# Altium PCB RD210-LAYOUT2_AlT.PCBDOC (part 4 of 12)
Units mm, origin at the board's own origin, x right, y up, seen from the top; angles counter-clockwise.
Board outline 250 x 123 mm, 4 copper layers (TOP, Mid-Layer 1, Mid-Layer 2, BOTTOM), stack 0.711 mm thick; 1043 components, 659 nets, 2786 pads, 1228 vias.
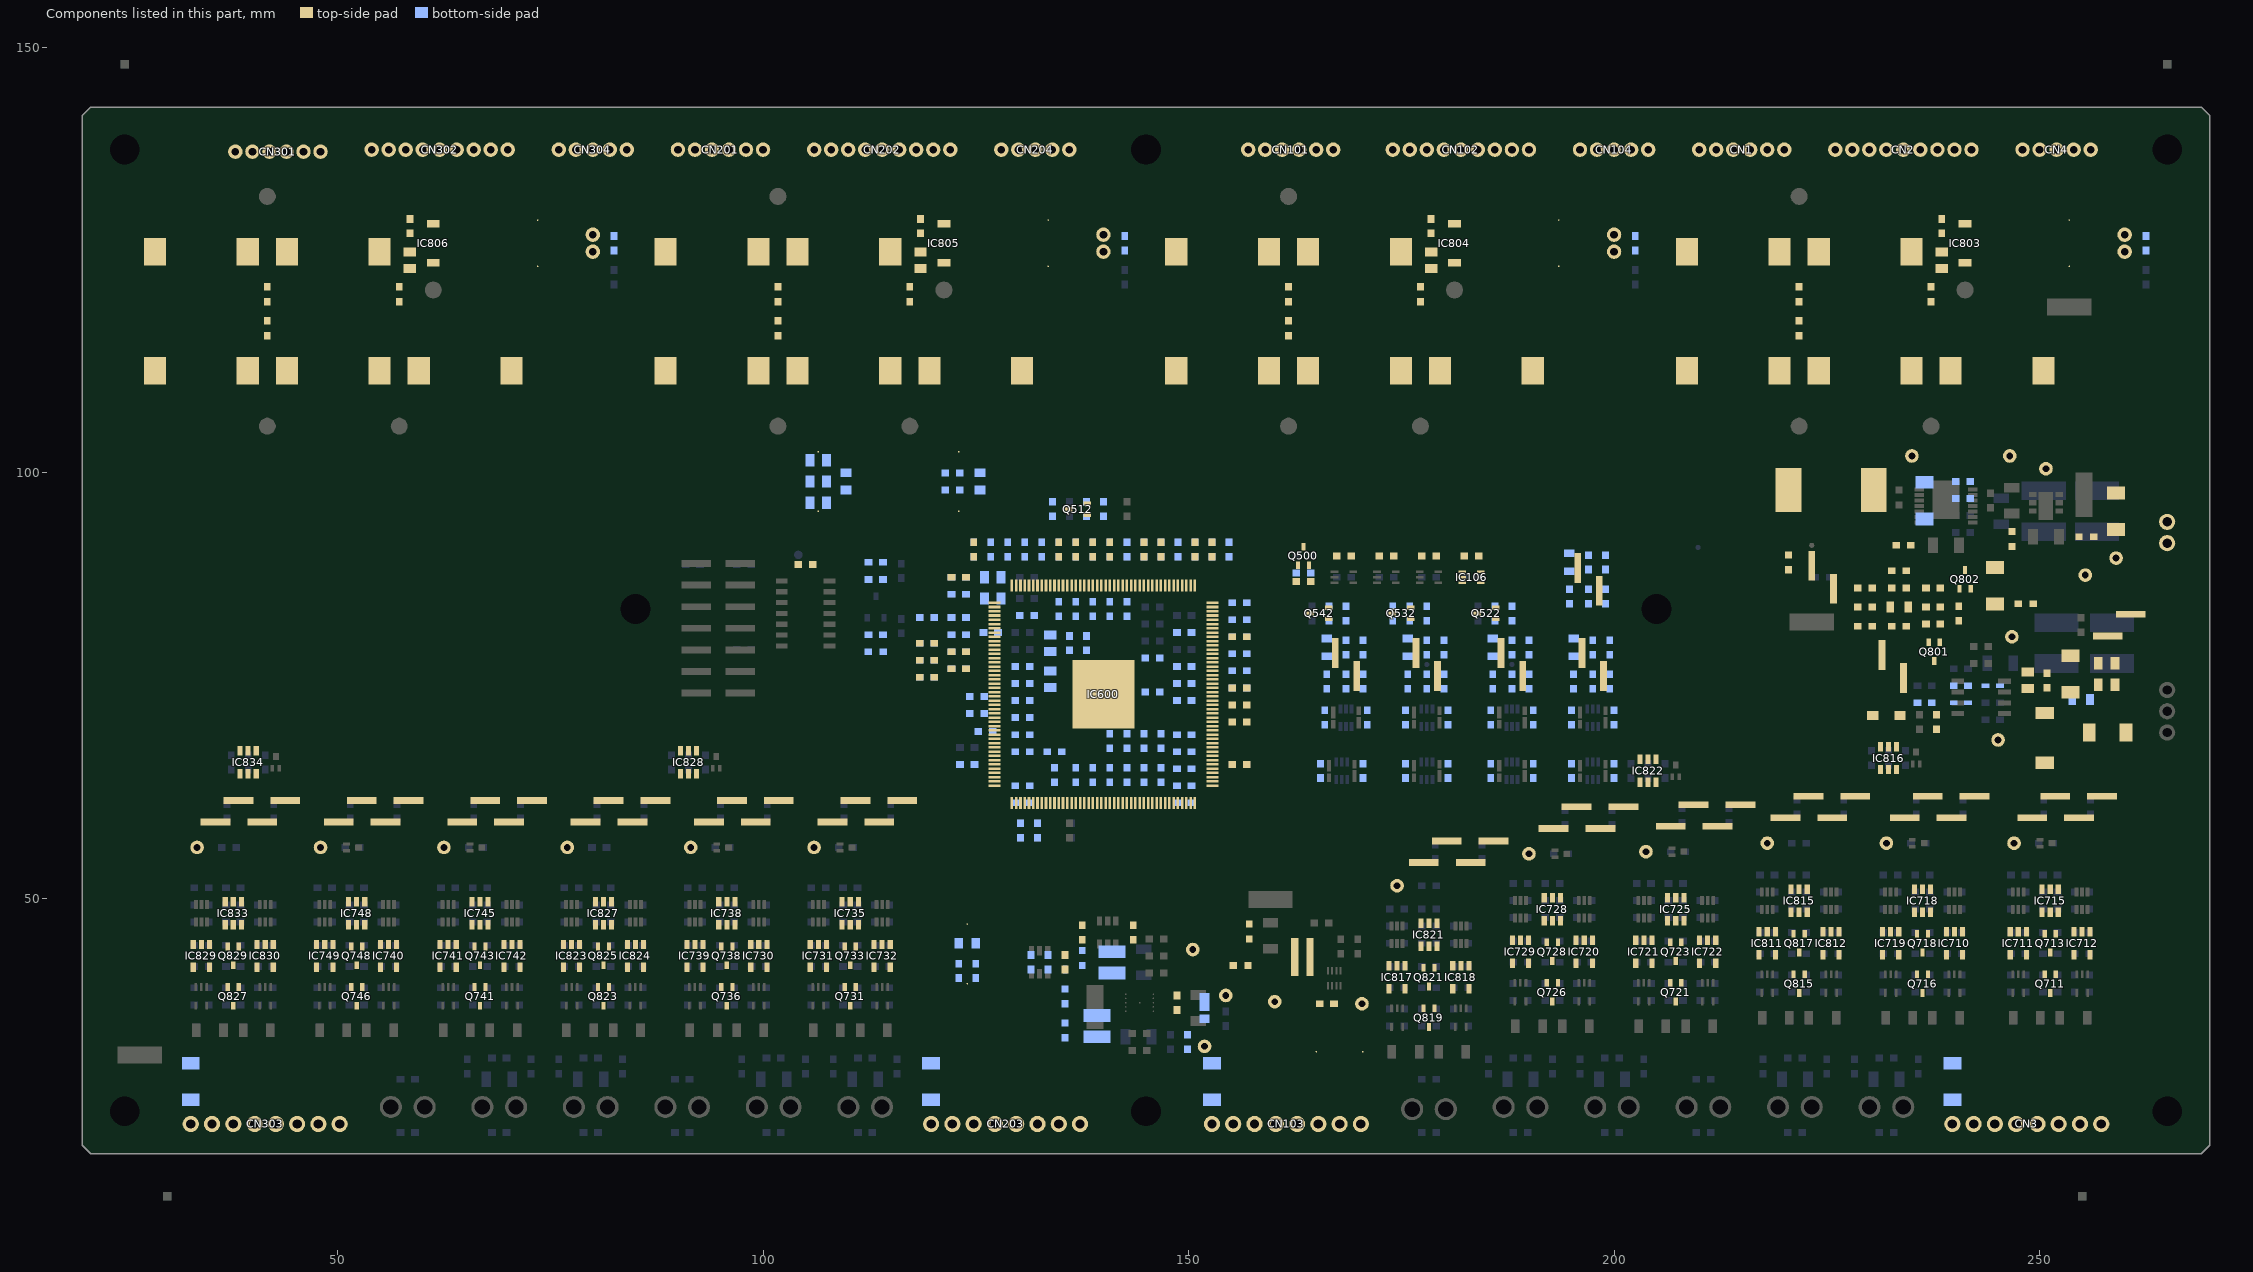
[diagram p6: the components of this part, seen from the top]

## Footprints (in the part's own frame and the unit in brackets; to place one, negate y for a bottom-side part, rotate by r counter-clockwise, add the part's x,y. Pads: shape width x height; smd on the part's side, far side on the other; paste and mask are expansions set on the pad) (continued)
_RS73G1JTTD1002F_+19 [mm] "KC00080BKP"
  rect 0.9x0.8 smd paste-0.9 mask+0: 1(0.85,0) 2(-0.85,0)
_RS73G1JTTD1002F_+20 [mm] "KC00080BKP"
  rect 0.9x0.8 smd paste-0.9 mask+0: 1(0.85,0) 2(-0.85,0)
_RS73G1JTTD1002F_+21 [mm] "KC00080BKP"
  rect 0.9x0.8 smd paste-0.9 mask+0: 1(0.85,0) 2(-0.85,0)
_RS73G1JTTD1002F_+22 [mm] "KC00080BKP"
  rect 0.9x0.8 smd paste-0.9 mask+0: 1(0.85,0) 2(-0.85,0)
_RS73G1JTTD1002F_+23 [mm] "KC00080BKP"
  rect 0.9x0.8 smd paste-0.9 mask+0: 1(0.85,0) 2(-0.85,0)
_RS73G1JTTD1002F_+24 [mm] "KC00080BKP"
  rect 0.9x0.8 smd paste-0.9 mask+0: 1(0.85,0) 2(-0.85,0)
_RS73G1JTTD1002F_+25 [mm] "KC00080BKP"
  rect 0.9x0.8 smd paste-0.9 mask+0: 1(0.85,0) 2(-0.85,0)
_RS73G1JTTD1002F_+26 [mm] "KC00080BKP"
  rect 0.9x0.8 smd paste-0.9 mask+0: 1(0.85,0) 2(-0.85,0)
_RS73G1JTTD1002F_+27 [mm] "KC00080BKP"
  rect 0.9x0.8 smd paste-0.9 mask+0: 1(0.85,0) 2(-0.85,0)
_RS73G1JTTD1002F_+28 [mm] "KC00080BKP"
  rect 0.9x0.8 smd paste-0.9 mask+0: 1(0.85,0) 2(-0.85,0)
_RS73G1JTTD1002F_+29 [mm] "KC00080BKP"
  rect 0.9x0.8 smd paste-0.9 mask+0: 1(0.85,0) 2(-0.85,0)
_RS73G1JTTD1002F_+30 [mm] "KC00080BKP"
  rect 0.9x0.8 smd paste-0.9 mask+0: 1(0.85,0) 2(-0.85,0)
_RS73G1JTTD1002F_+31 [mm] "KC00080BKP"
  rect 0.9x0.8 smd paste-0.9 mask+0: 1(-0.85,0) 2(0.85,0)
_RS73G1JTTD1002F_+32 [mm] "KC00080BKP"
  rect 0.9x0.8 smd paste-0.9 mask+0: 1(0.85,0) 2(-0.85,0)
_RS73G1JTTD1002F_+33 [mm] "KC00080BKP"
  rect 0.9x0.8 smd paste-0.9 mask+0: 1(0.85,0) 2(-0.85,0)
_RS73G1JTTD1002F_+34 [mm] "KC00080BKP"
  rect 0.9x0.8 smd paste-0.9 mask+0: 1(-0.85,0) 2(0.85,0)
_RS73G1JTTD1002F_+35 [mm] "KC00080BKP"
  rect 0.9x0.8 smd paste-0.9 mask+0: 1(0.85,0) 2(-0.85,0)
_RS73G1JTTD1002F_+36 [mm] "KC00080BKP"
  rect 0.9x0.8 smd paste-0.9 mask+0: 1(0.85,0) 2(-0.85,0)
_RS73G1JTTD1002F_+37 [mm] "KC00080BKP"
  rect 0.9x0.8 smd paste-0.9 mask+0: 1(0.85,0) 2(-0.85,0)
_RS73G1JTTD1002F_+38 [mm] "KC00080BKP"
  rect 0.9x0.8 smd paste-0.9 mask+0: 1(0.85,0) 2(-0.85,0)
_RS73G1JTTD1002F_+39 [mm] "KC00080BKP"
  rect 0.9x0.8 smd paste-0.9 mask+0: 1(0.85,0) 2(-0.85,0)
_RS73G1JTTD1002F_+40 [mm] "KC00080BKP"
  rect 0.9x0.8 smd paste-0.9 mask+0: 1(0.85,0) 2(-0.85,0)
_RS73G1JTTD1002F_+41 [mm] "KC00080BKP"
  rect 0.9x0.8 smd paste-0.9 mask+0: 1(0.85,0) 2(-0.85,0)
_RS73G1JTTD1002F_+42 [mm] "KC00080BKP"
  rect 0.9x0.8 smd paste-0.9 mask+0: 1(0.85,0) 2(-0.85,0)
_RS73G1JTTD1002F_+43 [mm] "KC00080BKP"
  rect 0.9x0.8 smd paste-0.9 mask+0: 1(0.85,0) 2(-0.85,0)
_RS73G1JTTD1002F_+44 [mm] "KC00080BKP"
  rect 0.9x0.8 smd paste-0.9 mask+0: 1(0.85,0) 2(-0.85,0)
_RS73G1JTTD1002F_+45 [mm] "KC00080BKP"
  rect 0.9x0.8 smd paste-0.9 mask+0: 1(0.85,0) 2(-0.85,0)
_RS73G1JTTD1002F_+46 [mm] "KC00080BKP"
  rect 0.9x0.8 smd paste-0.9 mask+0: 1(0.85,0) 2(-0.85,0)
_RS73G1JTTD1002F_+47 [mm] "KC00080BKP"
  rect 0.9x0.8 smd paste-0.9 mask+0: 1(0.85,0) 2(-0.85,0)
_RS73G1JTTD1601F_ [mm] "KC00080BKP"
  rect 0.9x0.8 smd paste-0.9 mask+0: 1(0.85,0) 2(-0.85,0)
_RS73G1JTTD1601F_+1 [mm] "KC00080BKP"
  rect 0.9x0.8 smd paste-0.9 mask+0: 1(0.85,0) 2(-0.85,0)
_RS73G1JTTD1601F_+2 [mm] "KC00080BKP"
  rect 0.9x0.8 smd paste-0.9 mask+0: 1(0.85,0) 2(-0.85,0)
_RS73G1JTTD1601F_+3 [mm] "KC00080BKP"
  rect 0.9x0.8 smd paste-0.9 mask+0: 1(0.85,0) 2(-0.85,0)
_RS73G1JTTD1601F_+4 [mm] "KC00080BKP"
  rect 0.9x0.8 smd paste-0.9 mask+0: 1(0.85,0) 2(-0.85,0)
_RS73G1JTTD1601F_+5 [mm] "KC00080BKP"
  rect 0.9x0.8 smd paste-0.9 mask+0: 1(0.85,0) 2(-0.85,0)
_RS73G1JTTD1601F_+6 [mm] "KC00080BKP"
  rect 0.9x0.8 smd paste-0.9 mask+0: 1(0.85,0) 2(-0.85,0)
_RS73G1JTTD1601F_+7 [mm] "KC00080BKP"
  rect 0.9x0.8 smd paste-0.9 mask+0: 1(0.85,0) 2(-0.85,0)
_RS73G1JTTD2201F_ [mm] "KC00080BKP"
  rect 0.9x0.8 smd paste-0.9 mask+0: 1(0.85,0) 2(-0.85,0)
_RS73G1JTTD2201F_+1 [mm] "KC00080BKP"
  rect 0.9x0.8 smd paste-0.9 mask+0: 1(0.85,0) 2(-0.85,0)
_RS73G1JTTD2201F_+2 [mm] "KC00080BKP"
  rect 0.9x0.8 smd paste-0.9 mask+0: 1(-0.85,0) 2(0.85,0)
_RS73G1JTTD2701F_ [mm] "KC00080BKP"
  rect 0.9x0.8 smd paste-0.9 mask+0: 1(0.85,0) 2(-0.85,0)
_RS73G1JTTD2701F_+1 [mm] "KC00080BKP"
  rect 0.9x0.8 smd paste-0.9 mask+0: 1(0.85,0) 2(-0.85,0)
_RS73G1JTTD2701F_+2 [mm] "KC00080BKP"
  rect 0.9x0.8 smd paste-0.9 mask+0: 1(0.85,0) 2(-0.85,0)
_RS73G1JTTD2701F_+3 [mm] "KC00080BKP"
  rect 0.9x0.8 smd paste-0.9 mask+0: 1(0.85,0) 2(-0.85,0)
_RS73G1JTTD4701F_ [mm] "KC00080BKP"
  rect 0.9x0.8 smd paste-0.9 mask+0: 1(-0.85,0) 2(0.85,0)
_RS73G1JTTD4701F_+1 [mm] "KC00080BKP"
  rect 0.9x0.8 smd paste-0.9 mask+0: 1(-0.85,0) 2(0.85,0)
_RS73G1JTTD4701F_+2 [mm] "KC00080BKP"
  rect 0.9x0.8 smd paste-0.9 mask+0: 1(-0.85,0) 2(0.85,0)
_RS73G1JTTD4701F_+3 [mm] "KC00080BKP"
  rect 0.9x0.8 smd paste-0.9 mask+0: 1(-0.85,0) 2(0.85,0)
_RS73G1JTTD4701F_+4 [mm] "KC00080BKP"
  rect 0.9x0.8 smd paste-0.9 mask+0: 1(-0.85,0) 2(0.85,0)
_RS73G1JTTD4701F_+5 [mm] "KC00080BKP"
  rect 0.9x0.8 smd paste-0.9 mask+0: 1(-0.85,0) 2(0.85,0)
_RS73G1JTTD4701F_+6 [mm] "KC00080BKP"
  rect 0.9x0.8 smd paste-0.9 mask+0: 1(-0.85,0) 2(0.85,0)
_RS73G1JTTD4701F_+7 [mm] "KC00080BKP"
  rect 0.9x0.8 smd paste-0.9 mask+0: 1(-0.85,0) 2(0.85,0)
_RS73G1JTTD4701F_+8 [mm] "KC00080BKP"
  rect 0.9x0.8 smd paste-0.9 mask+0: 1(0.85,0) 2(-0.85,0)
_RS73G1JTTD4701F_+9 [mm] "KC00080BKP"
  rect 0.9x0.8 smd paste-0.9 mask+0: 1(0.85,0) 2(-0.85,0)
_RS73G1JTTD4701F_+10 [mm] "KC00080BKP"
  rect 0.9x0.8 smd paste-0.9 mask+0: 1(0.85,0) 2(-0.85,0)
_RS73G1JTTD4701F_+11 [mm] "KC00080BKP"
  rect 0.9x0.8 smd paste-0.9 mask+0: 1(0.85,0) 2(-0.85,0)
_RS73G1JTTD4701F_+12 [mm] "KC00080BKP"
  rect 0.9x0.8 smd paste-0.9 mask+0: 1(-0.85,0) 2(0.85,0)
_RS73G1JTTD4701F_+13 [mm] "KC00080BKP"
  rect 0.9x0.8 smd paste-0.9 mask+0: 1(0.85,0) 2(-0.85,0)
_RS73G1JTTD4701F_+14 [mm] "KC00080BKP"
  rect 0.9x0.8 smd paste-0.9 mask+0: 1(-0.85,0) 2(0.85,0)
_RS73G1JTTD4701F_+15 [mm] "KC00080BKP"
  rect 0.9x0.8 smd paste-0.9 mask+0: 1(-0.85,0) 2(0.85,0)
_RS73G1JTTD5602F_ [mm] "KC00080BKP"
  rect 0.9x0.8 smd paste-0.9 mask+0: 1(0.85,0) 2(-0.85,0)
_RS73G1JTTD5602F_+1 [mm] "KC00080BKP"
  rect 0.9x0.8 smd paste-0.9 mask+0: 1(-0.85,0) 2(0.85,0)
_SG73P1JTTD1R60F_ [mm] "KC00080BKP"
  rect 0.9x0.8 smd paste-0.9 mask+0: 1(-0.85,0) 2(0.85,0)
_SG73P1JTTD1801F_ [mm] "KC00080BKP"
  rect 0.9x0.8 smd paste-0.9 mask+0: 1(0.85,0) 2(-0.85,0)
_SG73P1JTTD1801F_+1 [mm] "KC00080BKP"
  rect 0.9x0.8 smd paste-0.9 mask+0: 1(0.85,0) 2(-0.85,0)
_SG73P1JTTD1801F_+2 [mm] "KC00080BKP"
  rect 0.9x0.8 smd paste-0.9 mask+0: 1(0.85,0) 2(-0.85,0)
_SG73P1JTTD1801F_+3 [mm] "KC00080BKP"
  rect 0.9x0.8 smd paste-0.9 mask+0: 1(0.85,0) 2(-0.85,0)
_SG73P1JTTD1801F_+4 [mm] "KC00080BKP"
  rect 0.9x0.8 smd paste-0.9 mask+0: 1(0.85,0) 2(-0.85,0)
_SG73P1JTTD1801F_+5 [mm] "KC00080BKP"
  rect 0.9x0.8 smd paste-0.9 mask+0: 1(-0.85,0) 2(0.85,0)
_SG73P1JTTD2202F_ [mm] "KC00080BKP"
  rect 0.9x0.8 smd paste-0.9 mask+0: 1(-0.85,0) 2(0.85,0)
_SG73P1JTTD2202F_+1 [mm] "KC00080BKP"
  rect 0.9x0.8 smd paste-0.9 mask+0: 1(0.85,0) 2(-0.85,0)
_SG73P1JTTD2202F_+2 [mm] "KC00080BKP"
  rect 0.9x0.8 smd paste-0.9 mask+0: 1(0.85,0) 2(-0.85,0)
_SG73P1JTTD2202F_+3 [mm] "KC00080BKP"
  rect 0.9x0.8 smd paste-0.9 mask+0: 1(0.85,0) 2(-0.85,0)
_SG73P1JTTD2202F_+4 [mm] "KC00080BKP"
  rect 0.9x0.8 smd paste-0.9 mask+0: 1(0.85,0) 2(-0.85,0)
_SG73P1JTTD2202F_+5 [mm] "KC00080BKP"
  rect 0.9x0.8 smd paste-0.9 mask+0: 1(0.85,0) 2(-0.85,0)
_SG73P1JTTD2202F_+6 [mm] "KC00080BKP"
  rect 0.9x0.8 smd paste-0.9 mask+0: 1(0.85,0) 2(-0.85,0)
_SG73P1JTTD2202F_+7 [mm] "KC00080BKP"
  rect 0.9x0.8 smd paste-0.9 mask+0: 1(0.85,0) 2(-0.85,0)
_SG73P1JTTD2202F_+8 [mm] "KC00080BKP"
  rect 0.9x0.8 smd paste-0.9 mask+0: 1(0.85,0) 2(-0.85,0)
_SG73P1JTTD2202F_+9 [mm] "KC00080BKP"
  rect 0.9x0.8 smd paste-0.9 mask+0: 1(0.85,0) 2(-0.85,0)
_SG73P1JTTD2202F_+10 [mm] "KC00080BKP"
  rect 0.9x0.8 smd paste-0.9 mask+0: 1(-0.85,0) 2(0.85,0)
_SG73P1JTTD2202F_+11 [mm] "KC00080BKP"
  rect 0.9x0.8 smd paste-0.9 mask+0: 1(-0.85,0) 2(0.85,0)
_SG73P1JTTD2202F_+12 [mm] "KC00080BKP"
  rect 0.9x0.8 smd paste-0.9 mask+0: 1(-0.85,0) 2(0.85,0)
_SG73P1JTTD2202F_+13 [mm] "KC00080BKP"
  rect 0.9x0.8 smd paste-0.9 mask+0: 1(-0.85,0) 2(0.85,0)
_SG73P1JTTD8201F_ [mm] "KC00080BKP"
  rect 0.9x0.8 smd paste-0.9 mask+0: 1(0.85,0) 2(-0.85,0)
_SG73P1JTTD8201F_+1 [mm] "KC00080BKP"
  rect 0.9x0.8 smd paste-0.9 mask+0: 1(0.85,0) 2(-0.85,0)
_SG73P1JTTD8201F_+2 [mm] "KC00080BKP"
  rect 0.9x0.8 smd paste-0.9 mask+0: 1(0.85,0) 2(-0.85,0)
_SG73P1JTTD8201F_+3 [mm] "KC00080BKP"
  rect 0.9x0.8 smd paste-0.9 mask+0: 1(0.85,0) 2(-0.85,0)
_SG73P1JTTD8201F_+4 [mm] "KC00080BKP"
  rect 0.9x0.8 smd paste-0.9 mask+0: 1(0.85,0) 2(-0.85,0)
_SG73P1JTTD8201F_+5 [mm] "KC00080BKP"
  rect 0.9x0.8 smd paste-0.9 mask+0: 1(-0.85,0) 2(0.85,0)
_SG73P2ATTD100J_ [mm] "KC00080BKP"
  rect 0.9x1.25 smd paste-1.25 mask+0: 1(1.05,0) 2(-1.05,0)
_SG73P2ATTD101J_ [mm] "KC00080BKP"
  rect 0.9x1.25 smd paste-1.25 mask+0: 1(1.05,0) 2(-1.05,0)
_SG73P2ATTD101J_+1 [mm] "KC00080BKP"
  rect 0.9x1.25 smd paste-1.25 mask+0: 1(1.05,0) 2(-1.05,0)
_SG73P2ATTD101J_+2 [mm] "KC00080BKP"
  rect 0.9x1.25 smd paste-1.25 mask+0: 1(1.05,0) 2(-1.05,0)
_SG73P2ATTD101J_+3 [mm] "KC00080BKP"
  rect 0.9x1.25 smd paste-1.25 mask+0: 1(1.05,0) 2(-1.05,0)
_SG73P2ATTD101J_+4 [mm] "KC00080BKP"
  rect 0.9x1.25 smd paste-1.25 mask+0: 1(1.05,0) 2(-1.05,0)
_SG73P2ATTD101J_+5 [mm] "KC00080BKP"
  rect 0.9x1.25 smd paste-1.25 mask+0: 1(-1.05,0) 2(1.05,0)
_TLRZ1JTTD_ [mm] "KC00080BKP"
  rect 0.85x0.8 smd paste-0.85 mask+0: 1(-0.875,0) 2(0.875,0)
_TLRZ1JTTD_+1 [mm] "KC00080BKP"
  rect 0.85x0.8 smd paste-0.85 mask+0: 1(-0.875,0) 2(0.875,0)
_TLRZ1JTTD_+2 [mm] "KC00080BKP"
  rect 0.85x0.8 smd paste-0.85 mask+0: 1(-0.875,0) 2(0.875,0)
_TLRZ1JTTD_+3 [mm] "KC00080BKP"
  rect 0.85x0.8 smd paste-0.85 mask+0: 1(-0.875,0) 2(0.875,0)
_TLRZ1JTTD_+4 [mm] "KC00080BKP"
  rect 0.85x0.8 smd paste-0.85 mask+0: 1(-0.875,0) 2(0.875,0)
_TLRZ1JTTD_+5 [mm] "KC00080BKP"
  rect 0.85x0.8 smd paste-0.85 mask+0: 1(-0.875,0) 2(0.875,0)
_TLRZ1JTTD_+6 [mm] "KC00080BKP"
  rect 0.85x0.8 smd paste-0.85 mask+0: 1(-0.875,0) 2(0.875,0)
_TLRZ1JTTD_+7 [mm] "KC00080BKP"
  rect 0.85x0.8 smd paste-0.85 mask+0: 1(-0.875,0) 2(0.875,0)
_TLRZ1JTTD_+8 [mm] "KC00080BKP"
  rect 0.85x0.8 smd paste-0.85 mask+0: 1(-0.875,0) 2(0.875,0)
_TLRZ1JTTD_+9 [mm] "KC00080BKP"
  rect 0.85x0.8 smd paste-0.85 mask+0: 1(-0.875,0) 2(0.875,0)
_TLRZ1JTTD_+10 [mm] "KC00080BKP"
  rect 0.85x0.8 smd paste-0.85 mask+0: 1(-0.875,0) 2(0.875,0)
_TLRZ1JTTD_+11 [mm] "KC00080BKP"
  rect 0.85x0.8 smd paste-0.85 mask+0: 1(-0.875,0) 2(0.875,0)
_TLRZ1JTTD_+12 [mm] "KC00080BKP"
  rect 0.85x0.8 smd paste-0.85 mask+0: 1(-0.875,0) 2(0.875,0)
_TLRZ1JTTD_+13 [mm] "KC00080BKP"
  rect 0.85x0.8 smd paste-0.85 mask+0: 1(0.875,0) 2(-0.875,0)
_TLRZ1JTTD_+14 [mm] "KC00080BKP"
  rect 0.85x0.8 smd paste-0.85 mask+0: 1(-0.875,0) 2(0.875,0)
_TLRZ1JTTD_+15 [mm] "KC00080BKP"
  rect 0.85x0.8 smd paste-0.85 mask+0: 1(-0.875,0) 2(0.875,0)
_TLRZ1JTTD_+16 [mm] "KC00080BKP"
  rect 0.85x0.8 smd paste-0.85 mask+0: 1(0.875,0) 2(-0.875,0)
_TLRZ1JTTD_+17 [mm] "KC00080BKP"
  rect 0.85x0.8 smd paste-0.85 mask+0: 1(-0.875,0) 2(0.875,0)
_TLRZ1JTTD_+18 [mm] "KC00080BKP"
  rect 0.85x0.8 smd paste-0.85 mask+0: 1(-0.875,0) 2(0.875,0)
_TLRZ1JTTD_+19 [mm] "KC00080BKP"
  rect 0.85x0.8 smd paste-0.85 mask+0: 1(0.875,0) 2(-0.875,0)
_TLRZ1JTTD_+20 [mm] "KC00080BKP"
  rect 0.85x0.8 smd paste-0.85 mask+0: 1(-0.875,0) 2(0.875,0)
_TLRZ1JTTD_+21 [mm] "KC00080BKP"
  rect 0.85x0.8 smd paste-0.85 mask+0: 1(0.875,0) 2(-0.875,0)
_TLVH431AQDBVRQ1_ [mm] "KC00080BKP"
  rect 0.6x1.1 smd paste-1.1 mask+0: 1(-0.95,-1.35) 2(0,-1.35) 3(0.95,-1.35) 4(0.95,1.35) 5(-0.95,1.35)
_TLVH431AQDBVRQ1_+1 [mm] "KC00080BKP"
  rect 0.6x1.1 smd paste-1.1 mask+0: 1(-0.95,-1.35) 2(0,-1.35) 3(0.95,-1.35) 4(0.95,1.35) 5(-0.95,1.35)
_TLVH431AQDBVRQ1_+2 [mm] "KC00080BKP"
  rect 0.6x1.1 smd paste-1.1 mask+0: 1(-0.95,-1.35) 2(0,-1.35) 3(0.95,-1.35) 4(0.95,1.35) 5(-0.95,1.35)
_TLVH431AQDBVRQ1_+3 [mm] "KC00080BKP"
  rect 0.6x1.1 smd paste-1.1 mask+0: 1(-0.95,-1.35) 2(0,-1.35) 3(0.95,-1.35) 4(0.95,1.35) 5(-0.95,1.35)
_TLVH431AQDBVRQ1_+4 [mm] "KC00080BKP"
  rect 0.6x1.1 smd paste-1.1 mask+0: 1(-0.95,-1.35) 2(0,-1.35) 3(0.95,-1.35) 4(0.95,1.35) 5(-0.95,1.35)
_TLVH431AQDBVRQ1_+5 [mm] "KC00080BKP"
  rect 0.6x1.1 smd paste-1.1 mask+0: 1(-0.95,-1.35) 2(0,-1.35) 3(0.95,-1.35) 4(0.95,1.35) 5(-0.95,1.35)
_TLVH431AQDBVRQ1_+6 [mm] "KC00080BKP"
  rect 0.6x1.1 smd paste-1.1 mask+0: 1(-0.95,-1.35) 2(0,-1.35) 3(0.95,-1.35) 4(0.95,1.35) 5(-0.95,1.35)
_TLVH431AQDBVRQ1_+7 [mm] "KC00080BKP"
  rect 0.6x1.1 smd paste-1.1 mask+0: 1(-0.95,-1.35) 2(0,-1.35) 3(0.95,-1.35) 4(0.95,1.35) 5(-0.95,1.35)
_TLVH431AQDBVRQ1_+8 [mm] "KC00080BKP"
  rect 0.6x1.1 smd paste-1.1 mask+0: 1(-0.95,-1.35) 2(0,-1.35) 3(0.95,-1.35) 4(0.95,1.35) 5(-0.95,1.35)
_TLVH431AQDBVRQ1_+9 [mm] "KC00080BKP"
  rect 0.6x1.1 smd paste-1.1 mask+0: 1(-0.95,-1.35) 2(0,-1.35) 3(0.95,-1.35) 4(0.95,1.35) 5(-0.95,1.35)
_TLVH431AQDBVRQ1_+10 [mm] "KC00080BKP"
  rect 0.6x1.1 smd paste-1.1 mask+0: 1(-0.95,-1.35) 2(0,-1.35) 3(0.95,-1.35) 4(0.95,1.35) 5(-0.95,1.35)
_TLVH431AQDBVRQ1_+11 [mm] "KC00080BKP"
  rect 0.6x1.1 smd paste-1.1 mask+0: 1(-0.95,-1.35) 2(0,-1.35) 3(0.95,-1.35) 4(0.95,1.35) 5(-0.95,1.35)
_TLVH431AQDBVRQ1_+12 [mm] "KC00080BKP"
  rect 0.6x1.1 smd paste-1.1 mask+0: 1(-0.95,-1.35) 2(0,-1.35) 3(0.95,-1.35) 4(0.95,1.35) 5(-0.95,1.35)
_TLVH431AQDBVRQ1_+13 [mm] "KC00080BKP"
  rect 0.6x1.1 smd paste-1.1 mask+0: 1(-0.95,-1.35) 2(0,-1.35) 3(0.95,-1.35) 4(0.95,1.35) 5(-0.95,1.35)
_TLVH431AQDBVRQ1_+14 [mm] "KC00080BKP"
  rect 0.6x1.1 smd paste-1.1 mask+0: 1(-0.95,-1.35) 2(0,-1.35) 3(0.95,-1.35) 4(0.95,1.35) 5(-0.95,1.35)
_TLVH431AQDBVRQ1_+15 [mm] "KC00080BKP"
  rect 0.6x1.1 smd paste-1.1 mask+0: 1(-0.95,-1.35) 2(0,-1.35) 3(0.95,-1.35) 4(0.95,1.35) 5(-0.95,1.35)
_TLVH431AQDBVRQ1_+16 [mm] "KC00080BKP"
  rect 0.6x1.1 smd paste-1.1 mask+0: 1(-0.95,-1.35) 2(0,-1.35) 3(0.95,-1.35) 4(0.95,1.35) 5(-0.95,1.35)
_TLVH431AQDBVRQ1_+17 [mm] "KC00080BKP"
  rect 0.6x1.1 smd paste-1.1 mask+0: 1(-0.95,-1.35) 2(0,-1.35) 3(0.95,-1.35) 4(0.95,1.35) 5(-0.95,1.35)
_TLVH431AQDBVRQ1_+18 [mm] "KC00080BKP"
  rect 0.6x1.1 smd paste-1.1 mask+0: 1(-0.95,-1.35) 2(0,-1.35) 3(0.95,-1.35) 4(0.95,1.35) 5(-0.95,1.35)
_TLVH431AQDBVRQ1_+19 [mm] "KC00080BKP"
  rect 0.6x1.1 smd paste-1.1 mask+0: 1(-0.95,-1.35) 2(0,-1.35) 3(0.95,-1.35) 4(0.95,1.35) 5(-0.95,1.35)
_TLVH431AQDBVRQ1_+20 [mm] "KC00080BKP"
  rect 0.6x1.1 smd paste-1.1 mask+0: 1(-0.95,-1.35) 2(0,-1.35) 3(0.95,-1.35) 4(0.95,1.35) 5(-0.95,1.35)
_TLVH431AQDBVRQ1_+21 [mm] "KC00080BKP"
  rect 0.6x1.1 smd paste-1.1 mask+0: 1(-0.95,-1.35) 2(0,-1.35) 3(0.95,-1.35) 4(0.95,1.35) 5(-0.95,1.35)
_TLVH431AQDBVRQ1_+22 [mm] "KC00080BKP"
  rect 0.6x1.1 smd paste-1.1 mask+0: 1(-0.95,-1.35) 2(0,-1.35) 3(0.95,-1.35) 4(0.95,1.35) 5(-0.95,1.35)
_TLVH431AQDBVRQ1_+23 [mm] "KC00080BKP"
  rect 0.6x1.1 smd paste-1.1 mask+0: 1(-0.95,-1.35) 2(0,-1.35) 3(0.95,-1.35) 4(0.95,1.35) 5(-0.95,1.35)
_TMS320F28377SPTP_ [mm] "KC00080BKP"
  rect 0.3x1.4 smd paste-1.4 mask+0: 1(-10.75,-12.8) 2(-10.25,-12.8) 3(-9.75,-12.8) 4(-9.25,-12.8) 5(-8.75,-12.8) 6(-8.25,-12.8) 7(-7.75,-12.8) 8(-7.25,-12.8) 9(-6.75,-12.8) 10(-6.25,-12.8) 11(-5.75,-12.8) 12(-5.25,-12.8) 13(-4.75,-12.8) 14(-4.25,-12.8) 15(-3.75,-12.8) 16(-3.25,-12.8) 17(-2.75,-12.8) 18(-2.25,-12.8) 19(-1.75,-12.8) 20(-1.25,-12.8) 21(-0.75,-12.8) 22(-0.25,-12.8) 23(0.25,-12.8) 24(0.75,-12.8) 25(1.25,-12.8) 26(1.75,-12.8) 27(2.25,-12.8) 28(2.75,-12.8) 29(3.25,-12.8) 30(3.75,-12.8) 31(4.25,-12.8) 32(4.75,-12.8) 33(5.25,-12.8) 34(5.75,-12.8) 35(6.25,-12.8) 36(6.75,-12.8) 37(7.25,-12.8) 38(7.75,-12.8) 39(8.25,-12.8) 40(8.75,-12.8) 41(9.25,-12.8) 42(9.75,-12.8) 43(10.25,-12.8) 44(10.75,-12.8) 89(10.75,12.8) 90(10.25,12.8) 91(9.75,12.8) 92(9.25,12.8) 93(8.75,12.8) 94(8.25,12.8) 95(7.75,12.8) 96(7.25,12.8) 97(6.75,12.8) 98(6.25,12.8) 99(5.75,12.8) 100(5.25,12.8) 101(4.75,12.8) 102(4.25,12.8) 103(3.75,12.8) 104(3.25,12.8) 105(2.75,12.8) 106(2.25,12.8) 107(1.75,12.8) 108(1.25,12.8) 109(0.75,12.8) 110(0.25,12.8) 111(-0.25,12.8) 112(-0.75,12.8) 113(-1.25,12.8) 114(-1.75,12.8) 115(-2.25,12.8) 116(-2.75,12.8) 117(-3.25,12.8) 118(-3.75,12.8) 119(-4.25,12.8) 120(-4.75,12.8) 121(-5.25,12.8) 122(-5.75,12.8) 123(-6.25,12.8) 124(-6.75,12.8) 125(-7.25,12.8) 126(-7.75,12.8) 127(-8.25,12.8) 128(-8.75,12.8) 129(-9.25,12.8) 130(-9.75,12.8) 131(-10.25,12.8) 132(-10.75,12.8)
  rect 1.4x0.3 smd paste-1.4 mask+0: 45(12.8,-10.75) 46(12.8,-10.25) 47(12.8,-9.75) 48(12.8,-9.25) 49(12.8,-8.75) 50(12.8,-8.25) 51(12.8,-7.75) 52(12.8,-7.25) 53(12.8,-6.75) 54(12.8,-6.25) 55(12.8,-5.75) 56(12.8,-5.25) 57(12.8,-4.75) 58(12.8,-4.25) 59(12.8,-3.75) 60(12.8,-3.25) 61(12.8,-2.75) 62(12.8,-2.25) 63(12.8,-1.75) 64(12.8,-1.25) 65(12.8,-0.75) 66(12.8,-0.25) 67(12.8,0.25) 68(12.8,0.75) 69(12.8,1.25) 70(12.8,1.75) 71(12.8,2.25) 72(12.8,2.75) 73(12.8,3.25) 74(12.8,3.75) 75(12.8,4.25) 76(12.8,4.75) 77(12.8,5.25) 78(12.8,5.75) 79(12.8,6.25) 80(12.8,6.75) 81(12.8,7.25) 82(12.8,7.75) 83(12.8,8.25) 84(12.8,8.75) 85(12.8,9.25) 86(12.8,9.75) 87(12.8,10.25) 88(12.8,10.75) 133(-12.8,10.75) 134(-12.8,10.25) 135(-12.8,9.75) 136(-12.8,9.25) 137(-12.8,8.75) 138(-12.8,8.25) 139(-12.8,7.75) 140(-12.8,7.25) 141(-12.8,6.75) 142(-12.8,6.25) 143(-12.8,5.75) 144(-12.8,5.25) 145(-12.8,4.75) 146(-12.8,4.25) 147(-12.8,3.75) 148(-12.8,3.25) 149(-12.8,2.75) 150(-12.8,2.25) 151(-12.8,1.75) 152(-12.8,1.25) 153(-12.8,0.75) 154(-12.8,0.25) 155(-12.8,-0.25) 156(-12.8,-0.75) 157(-12.8,-1.25) 158(-12.8,-1.75) 159(-12.8,-2.25) 160(-12.8,-2.75) 161(-12.8,-3.25) 162(-12.8,-3.75) 163(-12.8,-4.25) 164(-12.8,-4.75) 165(-12.8,-5.25) 166(-12.8,-5.75) 167(-12.8,-6.25) 168(-12.8,-6.75) 169(-12.8,-7.25) 170(-12.8,-7.75) 171(-12.8,-8.25) 172(-12.8,-8.75) 173(-12.8,-9.25) 174(-12.8,-9.75) 175(-12.8,-10.25) 176(-12.8,-10.75)
  rect 7.3x8 smd paste-8 mask+0: 177(0,0)
_TS5A3159QDBVRQ1_ [mm] "KC00080BKP"
  rect 0.6x1.1 smd paste-1.1 mask+0: 1(-0.95,-1.35) 2(0,-1.35) 3(0.95,-1.35) 4(0.95,1.35) 5(0,1.35) 6(-0.95,1.35)
_TS5A3159QDBVRQ1_+1 [mm] "KC00080BKP"
  rect 0.6x1.1 smd paste-1.1 mask+0: 1(-0.95,-1.35) 2(0,-1.35) 3(0.95,-1.35) 4(0.95,1.35) 5(0,1.35) 6(-0.95,1.35)
_TS5A3159QDBVRQ1_+2 [mm] "KC00080BKP"
  rect 0.6x1.1 smd paste-1.1 mask+0: 1(-0.95,-1.35) 2(0,-1.35) 3(0.95,-1.35) 4(0.95,1.35) 5(0,1.35) 6(-0.95,1.35)
_TS5A3159QDBVRQ1_+3 [mm] "KC00080BKP"
  rect 0.6x1.1 smd paste-1.1 mask+0: 1(-0.95,-1.35) 2(0,-1.35) 3(0.95,-1.35) 4(0.95,1.35) 5(0,1.35) 6(-0.95,1.35)
_TS5A3159QDBVRQ1_+4 [mm] "KC00080BKP"
  rect 0.6x1.1 smd paste-1.1 mask+0: 1(-0.95,-1.35) 2(0,-1.35) 3(0.95,-1.35) 4(0.95,1.35) 5(0,1.35) 6(-0.95,1.35)
_TS5A3159QDBVRQ1_+5 [mm] "KC00080BKP"
  rect 0.6x1.1 smd paste-1.1 mask+0: 1(-0.95,-1.35) 2(0,-1.35) 3(0.95,-1.35) 4(0.95,1.35) 5(0,1.35) 6(-0.95,1.35)
_TS5A3159QDBVRQ1_+6 [mm] "KC00080BKP"
  rect 0.6x1.1 smd paste-1.1 mask+0: 1(-0.95,-1.35) 2(0,-1.35) 3(0.95,-1.35) 4(0.95,1.35) 5(0,1.35) 6(-0.95,1.35)
_TS5A3159QDBVRQ1_+7 [mm] "KC00080BKP"
  rect 0.6x1.1 smd paste-1.1 mask+0: 1(-0.95,-1.35) 2(0,-1.35) 3(0.95,-1.35) 4(0.95,1.35) 5(0,1.35) 6(-0.95,1.35)
_TS5A3159QDBVRQ1_+8 [mm] "KC00080BKP"
  rect 0.6x1.1 smd paste-1.1 mask+0: 1(-0.95,-1.35) 2(0,-1.35) 3(0.95,-1.35) 4(0.95,1.35) 5(0,1.35) 6(-0.95,1.35)
_TS5A3159QDBVRQ1_+9 [mm] "KC00080BKP"
  rect 0.6x1.1 smd paste-1.1 mask+0: 1(-0.95,-1.35) 2(0,-1.35) 3(0.95,-1.35) 4(0.95,1.35) 5(0,1.35) 6(-0.95,1.35)
_TS5A3159QDBVRQ1_+10 [mm] "KC00080BKP"
  rect 0.6x1.1 smd paste-1.1 mask+0: 1(-0.95,-1.35) 2(0,-1.35) 3(0.95,-1.35) 4(0.95,1.35) 5(0,1.35) 6(-0.95,1.35)
_TS5A3159QDBVRQ1_+11 [mm] "KC00080BKP"
  rect 0.6x1.1 smd paste-1.1 mask+0: 1(-0.95,-1.35) 2(0,-1.35) 3(0.95,-1.35) 4(0.95,1.35) 5(0,1.35) 6(-0.95,1.35)
_TS5A3159QDBVRQ1_+12 [mm] "KC00080BKP"
  rect 0.6x1.1 smd paste-1.1 mask+0: 1(-0.95,-1.35) 2(0,-1.35) 3(0.95,-1.35) 4(0.95,1.35) 5(0,1.35) 6(-0.95,1.35)
_TS5A3159QDBVRQ1_+13 [mm] "KC00080BKP"
  rect 0.6x1.1 smd paste-1.1 mask+0: 1(-0.95,-1.35) 2(0,-1.35) 3(0.95,-1.35) 4(0.95,1.35) 5(0,1.35) 6(-0.95,1.35)
_TS5A3159QDBVRQ1_+14 [mm] "KC00080BKP"
  rect 0.6x1.1 smd paste-1.1 mask+0: 1(-0.95,-1.35) 2(0,-1.35) 3(0.95,-1.35) 4(0.95,1.35) 5(0,1.35) 6(-0.95,1.35)
_TS5A3159QDBVRQ1_+15 [mm] "KC00080BKP"
  rect 0.6x1.1 smd paste-1.1 mask+0: 1(-0.95,-1.35) 2(0,-1.35) 3(0.95,-1.35) 4(0.95,1.35) 5(0,1.35) 6(-0.95,1.35)
_TSW-101-07-G-S_ [mm] "KC00080BKP"
  round 1.6 hole 0.8 paste-1.7 mask+0: 1(0,0)
D2P_CN-5.9x4.5x6-PX2-H0.9 [mm] "KC00080BKP"
  round 1.7 hole 0.9 paste-1.8 mask+0: 1(1,0) 2(-1,0)
D2P_CN-7.4x5.75x7-PX2.5-H1.1 [mm] "KC00080BKP"
  round 1.9 hole 1.1 paste-2 mask+0: 1(1.25,0) 2(-1.25,0)
D5P_CN-11.9x4.5x6-PX2-H0.9 [mm] "KC00080BKP"
  round 1.7 hole 0.9 paste-1.8 mask+0: 1(4,0) 2(2,0) 3(0,0) 4(-2,0) 5(-4,0)
D6P_CN-13.9x4.5x6-PX2-H0.9 [mm] "KC00080BKP"
  round 1.7 hole 0.9 paste-1.8 mask+0: 1(5,0) 2(3,0) 3(1,0) 4(-1,0) 5(-3,0) 6(-5,0)
D8P_CN-22.4x5.75x7-PX2.5-H1.1 [mm] "KC00080BKP"
  round 1.9 hole 1.1 paste-2 mask+0: 1(8.75,0) 2(6.25,0) 3(3.75,0) 4(1.25,0) 5(-1.25,0) 6(-3.75,0) 7(-6.25,0) 8(-8.75,0)
D9P_CN-19.9x4.5x6-PX2-H0.9 [mm] "KC00080BKP"
  round 1.7 hole 0.9 paste-1.8 mask+0: 1(8,0) 2(6,0) 3(4,0) 4(2,0) 5(0,0) 6(-2,0) 7(-4,0) 8(-6,0) 9(-8,0)
S2P_CC-1.6x0.8x0.8-PX1.6 [mm] "KC00080BKP"
  rect 0.9x0.8 smd paste-0.9 mask+0: 1(0.85,0) 2(-0.85,0)
S2P_CC-1.6x0.8x0.8-PX1.6+1 [mm] "KC00080BKP"
  rect 0.9x0.8 smd paste-0.9 mask+0: 1(0.85,0) 2(-0.85,0)
S2P_CC-1.6x0.8x0.8-PX1.6+2 [mm] "KC00080BKP"
  rect 0.9x0.8 smd paste-0.9 mask+0: 1(0.85,0) 2(-0.85,0)
S2P_CC-1.6x0.8x0.8-PX1.6+3 [mm] "KC00080BKP"
  rect 0.9x0.8 smd paste-0.9 mask+0: 1(0.85,0) 2(-0.85,0)
S2P_CC-1.6x0.8x0.8-PX1.6+4 [mm] "KC00080BKP"
  rect 0.9x0.8 smd paste-0.9 mask+0: 1(0.85,0) 2(-0.85,0)
S2P_CC-1.6x0.8x0.8-PX1.6+5 [mm] "KC00080BKP"
  rect 0.9x0.8 smd paste-0.9 mask+0: 1(0.85,0) 2(-0.85,0)
S2P_CC-1.6x0.8x0.8-PX1.6+6 [mm] "KC00080BKP"
  rect 0.9x0.8 smd paste-0.9 mask+0: 1(0.85,0) 2(-0.85,0)
S2P_CC-1.6x0.8x0.8-PX1.6+7 [mm] "KC00080BKP"
  rect 0.9x0.8 smd paste-0.9 mask+0: 1(0.85,0) 2(-0.85,0)
S2P_CC-1.6x0.8x0.8-PX1.6+8 [mm] "KC00080BKP"
  rect 0.9x0.8 smd paste-0.9 mask+0: 1(0.85,0) 2(-0.85,0)
S2P_CC-1.6x0.8x0.8-PX1.6+9 [mm] "KC00080BKP"
  rect 0.9x0.8 smd paste-0.9 mask+0: 1(0.85,0) 2(-0.85,0)
S2P_CC-1.6x0.8x0.8-PX1.6+10 [mm] "KC00080BKP"
  rect 0.9x0.8 smd paste-0.9 mask+0: 1(0.85,0) 2(-0.85,0)
S2P_CC-1.6x0.8x0.8-PX1.6+11 [mm] "KC00080BKP"
  rect 0.9x0.8 smd paste-0.9 mask+0: 1(-0.85,0) 2(0.85,0)
S2P_CC-1.6x0.8x0.8-PX1.6+12 [mm] "KC00080BKP"
  rect 0.9x0.8 smd paste-0.9 mask+0: 1(-0.85,0) 2(0.85,0)
S2P_CC-1.6x0.8x0.8-PX1.6+13 [mm] "KC00080BKP"
  rect 0.9x0.8 smd paste-0.9 mask+0: 1(0.85,0) 2(-0.85,0)
S2P_CC-1.6x0.8x0.8-PX1.6+14 [mm] "KC00080BKP"
  rect 0.9x0.8 smd paste-0.9 mask+0: 1(-0.85,0) 2(0.85,0)
S2P_CC-1.6x0.8x0.8-PX1.6+15 [mm] "KC00080BKP"
  rect 0.9x0.8 smd paste-0.9 mask+0: 1(-0.85,0) 2(0.85,0)
S2P_CC-1.6x0.8x0.8-PX1.6+16 [mm] "KC00080BKP"
  rect 0.9x0.8 smd paste-0.9 mask+0: 1(-0.85,0) 2(0.85,0)
S2P_CC-1.6x0.8x0.8-PX1.6+17 [mm] "KC00080BKP"
  rect 0.9x0.8 smd paste-0.9 mask+0: 1(0.85,0) 2(-0.85,0)
S2P_CC-1.6x0.8x0.8-PX1.6+18 [mm] "KC00080BKP"
  rect 0.9x0.8 smd paste-0.9 mask+0: 1(-0.85,0) 2(0.85,0)
S2P_CC-1.6x0.8x0.8-PX1.6+19 [mm] "KC00080BKP"
  rect 0.9x0.8 smd paste-0.9 mask+0: 1(-0.85,0) 2(0.85,0)
S2P_CC-1.6x0.8x0.8-PX1.6+20 [mm] "KC00080BKP"
  rect 0.9x0.8 smd paste-0.9 mask+0: 1(-0.85,0) 2(0.85,0)
S2P_CC-1.6x0.8x0.8-PX1.6+21 [mm] "KC00080BKP"
  rect 0.9x0.8 smd paste-0.9 mask+0: 1(-0.85,0) 2(0.85,0)
S2P_CC-1.6x0.8x0.8-PX1.6+22 [mm] "KC00080BKP"
  rect 0.9x0.8 smd paste-0.9 mask+0: 1(0.85,0) 2(-0.85,0)
S2P_CC-1.6x0.8x0.8-PX1.6+23 [mm] "KC00080BKP"
  rect 0.9x0.8 smd paste-0.9 mask+0: 1(-0.85,0) 2(0.85,0)
S2P_CC-1.6x0.8x0.8-PX1.6+24 [mm] "KC00080BKP"
  rect 0.9x0.8 smd paste-0.9 mask+0: 1(0.85,0) 2(-0.85,0)
S2P_CC-1.6x0.8x0.8-PX1.6+25 [mm] "KC00080BKP"
  rect 0.9x0.8 smd paste-0.9 mask+0: 1(0.85,0) 2(-0.85,0)
S2P_CC-1.6x0.8x0.8-PX1.6+26 [mm] "KC00080BKP"
  rect 0.9x0.8 smd paste-0.9 mask+0: 1(0.85,0) 2(-0.85,0)
S2P_CC-1.6x0.8x0.8-PX1.6+27 [mm] "KC00080BKP"
  rect 0.9x0.8 smd paste-0.9 mask+0: 1(-0.85,0) 2(0.85,0)
S2P_CC-1.6x0.8x0.8-PX1.6+28 [mm] "KC00080BKP"
  rect 0.9x0.8 smd paste-0.9 mask+0: 1(0.85,0) 2(-0.85,0)
S2P_CC-1.6x0.8x0.8-PX1.6+29 [mm] "KC00080BKP"
  rect 0.9x0.8 smd paste-0.9 mask+0: 1(0.85,0) 2(-0.85,0)
S2P_CC-1.6x0.8x0.8-PX1.6+30 [mm] "KC00080BKP"
  rect 0.9x0.8 smd paste-0.9 mask+0: 1(0.85,0) 2(-0.85,0)
S2P_CC-1.6x0.8x0.8-PX1.6+31 [mm] "KC00080BKP"
  rect 0.9x0.8 smd paste-0.9 mask+0: 1(0.85,0) 2(-0.85,0)
S2P_CC-1.6x0.8x0.8-PX1.6+32 [mm] "KC00080BKP"
  rect 0.9x0.8 smd paste-0.9 mask+0: 1(0.85,0) 2(-0.85,0)
S2P_CC-1.6x0.8x0.8-PX1.6+33 [mm] "KC00080BKP"
  rect 0.9x0.8 smd paste-0.9 mask+0: 1(0.85,0) 2(-0.85,0)
S2P_CC-1.6x0.8x0.8-PX1.6+34 [mm] "KC00080BKP"
  rect 0.9x0.8 smd paste-0.9 mask+0: 1(0.85,0) 2(-0.85,0)
S2P_CC-1.6x0.8x0.8-PX1.6+35 [mm] "KC00080BKP"
  rect 0.9x0.8 smd paste-0.9 mask+0: 1(0.85,0) 2(-0.85,0)
S2P_CC-1.6x0.8x0.8-PX1.6+36 [mm] "KC00080BKP"
  rect 0.9x0.8 smd paste-0.9 mask+0: 1(0.85,0) 2(-0.85,0)
S2P_CC-1.6x0.8x0.8-PX1.6+37 [mm] "KC00080BKP"
  rect 0.9x0.8 smd paste-0.9 mask+0: 1(0.85,0) 2(-0.85,0)
S2P_CC-1.6x0.8x0.8-PX1.6+38 [mm] "KC00080BKP"
  rect 0.9x0.8 smd paste-0.9 mask+0: 1(0.85,0) 2(-0.85,0)
S2P_CC-1.6x0.8x0.8-PX1.6+39 [mm] "KC00080BKP"
  rect 0.9x0.8 smd paste-0.9 mask+0: 1(0.85,0) 2(-0.85,0)
S2P_CC-1.6x0.8x0.8-PX1.6+40 [mm] "KC00080BKP"
  rect 0.9x0.8 smd paste-0.9 mask+0: 1(0.85,0) 2(-0.85,0)
S2P_CC-1.6x0.8x0.8-PX1.6+41 [mm] "KC00080BKP"
  rect 0.9x0.8 smd paste-0.9 mask+0: 1(0.85,0) 2(-0.85,0)
S2P_CC-1.6x0.8x0.8-PX1.6+42 [mm] "KC00080BKP"
  rect 0.9x0.8 smd paste-0.9 mask+0: 1(0.85,0) 2(-0.85,0)
S2P_CC-1.6x0.8x0.8-PX1.6+43 [mm] "KC00080BKP"
  rect 0.9x0.8 smd paste-0.9 mask+0: 1(0.85,0) 2(-0.85,0)
S2P_CC-1.6x0.8x0.8-PX1.6+44 [mm] "KC00080BKP"
  rect 0.9x0.8 smd paste-0.9 mask+0: 1(0.85,0) 2(-0.85,0)
S2P_CC-1.6x0.8x0.8-PX1.6+45 [mm] "KC00080BKP"
  rect 0.9x0.8 smd paste-0.9 mask+0: 1(0.85,0) 2(-0.85,0)
S2P_CC-1.6x0.8x0.8-PX1.6+46 [mm] "KC00080BKP"
  rect 0.9x0.8 smd paste-0.9 mask+0: 1(0.85,0) 2(-0.85,0)
S2P_CC-1.6x0.8x0.8-PX1.6+47 [mm] "KC00080BKP"
  rect 0.9x0.8 smd paste-0.9 mask+0: 1(0.85,0) 2(-0.85,0)
S2P_CC-1.6x0.8x0.8-PX1.6+48 [mm] "KC00080BKP"
  rect 0.9x0.8 smd paste-0.9 mask+0: 1(0.85,0) 2(-0.85,0)
S2P_CC-1.6x0.8x0.8-PX1.6+49 [mm] "KC00080BKP"
  rect 0.9x0.8 smd paste-0.9 mask+0: 1(0.85,0) 2(-0.85,0)
S2P_CC-1.6x0.8x0.8-PX1.6+50 [mm] "KC00080BKP"
  rect 0.9x0.8 smd paste-0.9 mask+0: 1(0.85,0) 2(-0.85,0)
S2P_CC-1.6x0.8x0.8-PX1.6+51 [mm] "KC00080BKP"
  rect 0.9x0.8 smd paste-0.9 mask+0: 1(0.85,0) 2(-0.85,0)
S2P_CC-1.6x0.8x0.8-PX1.6+52 [mm] "KC00080BKP"
  rect 0.9x0.8 smd paste-0.9 mask+0: 1(0.85,0) 2(-0.85,0)
S2P_CC-1.6x0.8x0.8-PX1.6+53 [mm] "KC00080BKP"
  rect 0.9x0.8 smd paste-0.9 mask+0: 1(0.85,0) 2(-0.85,0)
S2P_CC-1.6x0.8x0.8-PX1.6+54 [mm] "KC00080BKP"
  rect 0.9x0.8 smd paste-0.9 mask+0: 1(0.85,0) 2(-0.85,0)
S2P_CC-1.6x0.8x0.8-PX1.6+55 [mm] "KC00080BKP"
  rect 0.9x0.8 smd paste-0.9 mask+0: 1(0.85,0) 2(-0.85,0)
S2P_CC-1.6x0.8x0.8-PX1.6+56 [mm] "KC00080BKP"
  rect 0.9x0.8 smd paste-0.9 mask+0: 1(0.85,0) 2(-0.85,0)
S2P_CC-1.6x0.8x0.8-PX1.6+57 [mm] "KC00080BKP"
  rect 0.9x0.8 smd paste-0.9 mask+0: 1(0.85,0) 2(-0.85,0)
S2P_CC-1.6x0.8x0.8-PX1.6+58 [mm] "KC00080BKP"
  rect 0.9x0.8 smd paste-0.9 mask+0: 1(0.85,0) 2(-0.85,0)
S2P_CC-1.6x0.8x0.8-PX1.6+59 [mm] "KC00080BKP"
  rect 0.9x0.8 smd paste-0.9 mask+0: 1(0.85,0) 2(-0.85,0)
S2P_CC-1.6x0.8x0.8-PX1.6+60 [mm] "KC00080BKP"
  rect 0.9x0.8 smd paste-0.9 mask+0: 1(0.85,0) 2(-0.85,0)
S2P_CC-1.6x0.8x0.8-PX1.6+61 [mm] "KC00080BKP"
  rect 0.9x0.8 smd paste-0.9 mask+0: 1(0.85,0) 2(-0.85,0)
S2P_CC-1.6x0.8x0.8-PX1.6+62 [mm] "KC00080BKP"
  rect 0.9x0.8 smd paste-0.9 mask+0: 1(0.85,0) 2(-0.85,0)
S2P_CC-1.6x0.8x0.8-PX1.6+63 [mm] "KC00080BKP"
  rect 0.9x0.8 smd paste-0.9 mask+0: 1(0.85,0) 2(-0.85,0)
S2P_CC-1.6x0.8x0.8-PX1.6+64 [mm] "KC00080BKP"
  rect 0.9x0.8 smd paste-0.9 mask+0: 1(0.85,0) 2(-0.85,0)
S2P_CC-1.6x0.8x0.8-PX1.6+65 [mm] "KC00080BKP"
  rect 0.9x0.8 smd paste-0.9 mask+0: 1(0.85,0) 2(-0.85,0)
S2P_CC-1.6x0.8x0.8-PX1.6+66 [mm] "KC00080BKP"
  rect 0.9x0.8 smd paste-0.9 mask+0: 1(0.85,0) 2(-0.85,0)
S2P_CC-1.6x0.8x0.8-PX1.6+67 [mm] "KC00080BKP"
  rect 0.9x0.8 smd paste-0.9 mask+0: 1(0.85,0) 2(-0.85,0)
S2P_CC-1.6x0.8x0.8-PX1.6+68 [mm] "KC00080BKP"
  rect 0.9x0.8 smd paste-0.9 mask+0: 1(0.85,0) 2(-0.85,0)
S2P_CC-1.6x0.8x0.8-PX1.6+69 [mm] "KC00080BKP"
  rect 0.9x0.8 smd paste-0.9 mask+0: 1(0.85,0) 2(-0.85,0)
S2P_CC-1.6x0.8x0.8-PX1.6+70 [mm] "KC00080BKP"
  rect 0.9x0.8 smd paste-0.9 mask+0: 1(0.85,0) 2(-0.85,0)
S2P_CC-1.6x0.8x0.8-PX1.6+71 [mm] "KC00080BKP"
  rect 0.9x0.8 smd paste-0.9 mask+0: 1(0.85,0) 2(-0.85,0)
S2P_CC-1.6x0.8x0.8-PX1.6+72 [mm] "KC00080BKP"
  rect 0.9x0.8 smd paste-0.9 mask+0: 1(0.85,0) 2(-0.85,0)
S2P_CC-1.6x0.8x0.8-PX1.6+73 [mm] "KC00080BKP"
  rect 0.9x0.8 smd paste-0.9 mask+0: 1(0.85,0) 2(-0.85,0)
S2P_CC-1.6x0.8x0.8-PX1.6+74 [mm] "KC00080BKP"
  rect 0.9x0.8 smd paste-0.9 mask+0: 1(0.85,0) 2(-0.85,0)
S2P_CC-1.6x0.8x0.8-PX1.6+75 [mm] "KC00080BKP"
  rect 0.9x0.8 smd paste-0.9 mask+0: 1(0.85,0) 2(-0.85,0)
S2P_CC-1.6x0.8x0.8-PX1.6+76 [mm] "KC00080BKP"
  rect 0.9x0.8 smd paste-0.9 mask+0: 1(0.85,0) 2(-0.85,0)
S2P_CC-1.6x0.8x0.8-PX1.6+77 [mm] "KC00080BKP"
  rect 0.9x0.8 smd paste-0.9 mask+0: 1(0.85,0) 2(-0.85,0)
S2P_CC-1.6x0.8x0.8-PX1.6+78 [mm] "KC00080BKP"
  rect 0.9x0.8 smd paste-0.9 mask+0: 1(0.85,0) 2(-0.85,0)
S2P_CC-1.6x0.8x0.8-PX1.6+79 [mm] "KC00080BKP"
  rect 0.9x0.8 smd paste-0.9 mask+0: 1(0.85,0) 2(-0.85,0)
S2P_CC-1.6x0.8x0.8-PX1.6+80 [mm] "KC00080BKP"
  rect 0.9x0.8 smd paste-0.9 mask+0: 1(-0.85,0) 2(0.85,0)
S2P_CC-1.6x0.8x0.8-PX1.6+81 [mm] "KC00080BKP"
  rect 0.9x0.8 smd paste-0.9 mask+0: 1(-0.85,0) 2(0.85,0)
S2P_CC-1.6x0.8x0.8-PX1.6+82 [mm] "KC00080BKP"
  rect 0.9x0.8 smd paste-0.9 mask+0: 1(-0.85,0) 2(0.85,0)
S2P_CC-1.6x0.8x0.8-PX1.6+83 [mm] "KC00080BKP"
  rect 0.9x0.8 smd paste-0.9 mask+0: 1(-0.85,0) 2(0.85,0)
S2P_CC-1.6x0.8x0.8-PX1.6+84 [mm] "KC00080BKP"
  rect 0.9x0.8 smd paste-0.9 mask+0: 1(-0.85,0) 2(0.85,0)
S2P_CC-1.6x0.8x0.8-PX1.6+85 [mm] "KC00080BKP"
  rect 0.9x0.8 smd paste-0.9 mask+0: 1(0.85,0) 2(-0.85,0)
S2P_CC-1.6x0.8x0.8-PX1.6+86 [mm] "KC00080BKP"
  rect 0.9x0.8 smd paste-0.9 mask+0: 1(0.85,0) 2(-0.85,0)
S2P_CC-1.6x0.8x0.8-PX1.6+87 [mm] "KC00080BKP"
  rect 0.9x0.8 smd paste-0.9 mask+0: 1(0.85,0) 2(-0.85,0)
S2P_CC-1.6x0.8x0.8-PX1.6+88 [mm] "KC00080BKP"
  rect 0.9x0.8 smd paste-0.9 mask+0: 1(0.85,0) 2(-0.85,0)
S2P_CC-1.6x0.8x0.8-PX1.6+89 [mm] "KC00080BKP"
  rect 0.9x0.8 smd paste-0.9 mask+0: 1(0.85,0) 2(-0.85,0)
S2P_CC-1.6x0.8x0.8-PX1.6+90 [mm] "KC00080BKP"
  rect 0.9x0.8 smd paste-0.9 mask+0: 1(0.85,0) 2(-0.85,0)
S2P_CC-1.6x0.8x0.8-PX1.6+91 [mm] "KC00080BKP"
  rect 0.9x0.8 smd paste-0.9 mask+0: 1(0.85,0) 2(-0.85,0)
S2P_CC-1.6x0.8x0.8-PX1.6+92 [mm] "KC00080BKP"
  rect 0.9x0.8 smd paste-0.9 mask+0: 1(0.85,0) 2(-0.85,0)
S2P_CC-1.6x0.8x0.8-PX1.6+93 [mm] "KC00080BKP"
  rect 0.9x0.8 smd paste-0.9 mask+0: 1(-0.85,0) 2(0.85,0)
S2P_CC-1.6x0.8x0.8-PX1.6+94 [mm] "KC00080BKP"
  rect 0.9x0.8 smd paste-0.9 mask+0: 1(-0.85,0) 2(0.85,0)
S2P_CC-1.6x0.8x0.8-PX1.6+95 [mm] "KC00080BKP"
  rect 0.9x0.8 smd paste-0.9 mask+0: 1(-0.85,0) 2(0.85,0)
S2P_CC-1.6x0.8x0.8-PX1.6+96 [mm] "KC00080BKP"
  rect 0.9x0.8 smd paste-0.9 mask+0: 1(-0.85,0) 2(0.85,0)
S2P_CC-1.6x0.8x0.8-PX1.6+97 [mm] "KC00080BKP"
  rect 0.9x0.8 smd paste-0.9 mask+0: 1(0.85,0) 2(-0.85,0)
S2P_CC-1.6x0.8x0.8-PX1.6+98 [mm] "KC00080BKP"
  rect 0.9x0.8 smd paste-0.9 mask+0: 1(0.85,0) 2(-0.85,0)
S2P_CC-1.6x0.8x0.8-PX1.6+99 [mm] "KC00080BKP"
  rect 0.9x0.8 smd paste-0.9 mask+0: 1(-0.85,0) 2(0.85,0)
S2P_CC-1.6x0.8x0.8-PX1.6+100 [mm] "KC00080BKP"
  rect 0.9x0.8 smd paste-0.9 mask+0: 1(0.85,0) 2(-0.85,0)
S2P_CC-1.6x0.8x0.8-PX1.6+101 [mm] "KC00080BKP"
  rect 0.9x0.8 smd paste-0.9 mask+0: 1(-0.85,0) 2(0.85,0)
S2P_CC-1.6x0.8x0.8-PX1.6+102 [mm] "KC00080BKP"
  rect 0.9x0.8 smd paste-0.9 mask+0: 1(-0.85,0) 2(0.85,0)
S2P_CC-1.6x0.8x0.8-PX1.6+103 [mm] "KC00080BKP"
  rect 0.9x0.8 smd paste-0.9 mask+0: 1(-0.85,0) 2(0.85,0)
S2P_CC-1.6x0.8x0.8-PX1.6+104 [mm] "KC00080BKP"
  rect 0.9x0.8 smd paste-0.9 mask+0: 1(-0.85,0) 2(0.85,0)
S2P_CC-1.6x0.8x0.8-PX1.6+105 [mm] "KC00080BKP"
  rect 0.9x0.8 smd paste-0.9 mask+0: 1(0.85,0) 2(-0.85,0)
S2P_CC-1.6x0.8x0.8-PX1.6+106 [mm] "KC00080BKP"
  rect 0.9x0.8 smd paste-0.9 mask+0: 1(0.85,0) 2(-0.85,0)
S2P_CC-2x1.25x1.25-PX2 [mm] "KC00080BKP"
  rect 1.05x1.45 smd paste-1.45 mask+0: 1(0.975,0) 2(-0.975,0)
S2P_CC-2x1.25x1.25-PX2+1 [mm] "KC00080BKP"
  rect 1.05x1.45 smd paste-1.45 mask+0: 1(0.975,0) 2(-0.975,0)
S2P_CC-2x1.25x1.25-PX2+2 [mm] "KC00080BKP"
  rect 1.05x1.45 smd paste-1.45 mask+0: 1(0.975,0) 2(-0.975,0)
S2P_CC-2x1.25x1.25-PX2+3 [mm] "KC00080BKP"
  rect 1.05x1.45 smd paste-1.45 mask+0: 1(0.975,0) 2(-0.975,0)
S2P_CC-2x1.25x1.25-PX2+4 [mm] "KC00080BKP"
  rect 1.05x1.45 smd paste-1.45 mask+0: 1(-0.975,0) 2(0.975,0)
S2P_CC-2x1.25x1.25-PX2+5 [mm] "KC00080BKP"
  rect 1.05x1.45 smd paste-1.45 mask+0: 1(-0.975,0) 2(0.975,0)
S2P_CC-2x1.25x1.25-PX2+6 [mm] "KC00080BKP"
  rect 1.05x1.45 smd paste-1.45 mask+0: 1(-0.975,0) 2(0.975,0)
S2P_CC-2x1.25x1.25-PX2+7 [mm] "KC00080BKP"
  rect 1.05x1.45 smd paste-1.45 mask+0: 1(-0.975,0) 2(0.975,0)
S2P_CC-2x1.25x1.25-PX2+8 [mm] "KC00080BKP"
  rect 1.05x1.45 smd paste-1.45 mask+0: 1(-0.975,0) 2(0.975,0)
S2P_CC-2x1.25x1.25-PX2+9 [mm] "KC00080BKP"
  rect 1.05x1.45 smd paste-1.45 mask+0: 1(0.975,0) 2(-0.975,0)
S2P_CC-2x1.25x1.25-PX2+10 [mm] "KC00080BKP"
  rect 1.05x1.45 smd paste-1.45 mask+0: 1(0.975,0) 2(-0.975,0)
S2P_CC-2x1.25x1.25-PX2+11 [mm] "KC00080BKP"
  rect 1.05x1.45 smd paste-1.45 mask+0: 1(0.975,0) 2(-0.975,0)
S2P_CC-2x1.25x1.25-PX2+12 [mm] "KC00080BKP"
  rect 1.05x1.45 smd paste-1.45 mask+0: 1(-0.975,0) 2(0.975,0)
S2P_CC-2x1.25x1.25-PX2+13 [mm] "KC00080BKP"
  rect 1.05x1.45 smd paste-1.45 mask+0: 1(-0.975,0) 2(0.975,0)
S2P_CE-6.6x6.6x5.8-PX7 [mil] "KC00080BKP"
  round 7 smd paste-7 mask+0: 1(-107.28,0) 2(107.28,0)
S2P_CE-6.6x6.6x5.8-PX7+1 [mil] "KC00080BKP"
  round 7 smd paste-7 mask+0: 1(-107.28,0) 2(107.28,0)
S2P_CE-6.6x6.6x5.8-PX7+2 [mil] "KC00080BKP"
  round 7 smd paste-7 mask+0: 1(-107.28,0) 2(107.28,0)
S2P_CE-6.6x6.6x5.8-PX7+3 [mil] "KC00080BKP"
  round 7 smd paste-7 mask+0: 1(-107.28,0) 2(107.28,0)
S2P_CE-6.6x6.6x5.8-PX7+4 [mil] "KC00080BKP"
  round 7 smd paste-7 mask+0: 1(-107.28,0) 2(107.28,0)
S2P_CE-8.3x8.3x10-PX8.9 [mil] "KC00080BKP"
  round 7 smd paste-7 mask+0: 1(-137.79,0) 2(137.8,0)
S2P_CE-8.3x8.3x10-PX8.9+1 [mil] "KC00080BKP"
  round 7 smd paste-7 mask+0: 1(-137.79,0) 2(137.79,0)
S2P_CE-8.3x8.3x10-PX8.9+2 [mil] "KC00080BKP"
  round 7 smd paste-7 mask+0: 1(-137.79,0) 2(137.79,0)
S2P_CN-5.08x2.54x9.65-PX2.54 [mm] "KC00080BKP"
  rect 0.8x3.5 smd paste-3.5 mask+0: 1(-1.27,1.35) 2(1.27,-1.35)
S2P_CN-5.08x2.54x9.65-PX2.54+1 [mm] "KC00080BKP"
  rect 0.8x3.5 smd paste-3.5 mask+0: 1(-1.27,1.35) 2(1.27,-1.35)
S2P_CN-5.08x2.54x9.65-PX2.54+2 [mm] "KC00080BKP"
  rect 0.8x3.5 smd paste-3.5 mask+0: 1(-1.27,1.35) 2(1.27,-1.35)
S2P_CN-5.08x2.54x9.65-PX2.54+3 [mm] "KC00080BKP"
  rect 0.8x3.5 smd paste-3.5 mask+0: 1(-1.27,1.35) 2(1.27,-1.35)
S2P_CN-5.08x2.54x9.65-PX2.54+4 [mm] "KC00080BKP"
  rect 0.8x3.5 smd paste-3.5 mask+0: 1(-1.27,1.35) 2(1.27,-1.35)
S2P_CN-5.08x2.54x9.65-PX2.54+5 [mm] "KC00080BKP"
  rect 0.8x3.5 smd paste-3.5 mask+0: 1(-1.27,1.35) 2(1.27,-1.35)
S2P_CN-5.08x2.54x9.65-PX2.54+6 [mm] "KC00080BKP"
  rect 0.8x3.5 smd paste-3.5 mask+0: 1(-1.27,1.35) 2(1.27,-1.35)
S2P_CN-5.08x2.54x9.65-PX2.54+7 [mm] "KC00080BKP"
  rect 0.8x3.5 smd paste-3.5 mask+0: 1(-1.27,1.35) 2(1.27,-1.35)
S2P_CN-5.08x2.54x9.65-PX2.54+8 [mm] "KC00080BKP"
  rect 0.8x3.5 smd paste-3.5 mask+0: 1(-1.27,1.35) 2(1.27,-1.35)
S2P_CN-5.08x2.54x9.65-PX2.54+9 [mm] "KC00080BKP"
  rect 0.8x3.5 smd paste-3.5 mask+0: 1(-1.27,1.35) 2(1.27,-1.35)
S2P_CN-5.08x2.54x9.65-PX2.54+10 [mm] "KC00080BKP"
  rect 0.8x3.5 smd paste-3.5 mask+0: 1(-1.27,1.35) 2(1.27,-1.35)
S2P_CN-5.08x2.54x9.65-PX2.54+11 [mm] "KC00080BKP"
  rect 0.8x3.5 smd paste-3.5 mask+0: 1(-1.27,1.35) 2(1.27,-1.35)
S2P_CN-5.08x2.54x9.65-PX2.54+12 [mm] "KC00080BKP"
  rect 0.8x3.5 smd paste-3.5 mask+0: 1(-1.27,1.35) 2(1.27,-1.35)
S2P_CN-5.08x2.54x9.65-PX2.54+13 [mm] "KC00080BKP"
  rect 0.8x3.5 smd paste-3.5 mask+0: 1(-1.27,1.35) 2(1.27,-1.35)
S2P_CN-5.08x2.54x9.65-PX2.54+14 [mm] "KC00080BKP"
  rect 0.8x3.5 smd paste-3.5 mask+0: 1(-1.27,1.35) 2(1.27,-1.35)
S2P_CN-5.08x2.54x9.65-PX2.54+15 [mm] "KC00080BKP"
  rect 0.8x3.5 smd paste-3.5 mask+0: 1(-1.27,1.35) 2(1.27,-1.35)
S2P_CN-5.08x2.54x9.65-PX2.54+16 [mm] "KC00080BKP"
  rect 0.8x3.5 smd paste-3.5 mask+0: 1(-1.27,1.35) 2(1.27,-1.35)
S2P_CN-5.08x2.54x9.65-PX2.54+17 [mm] "KC00080BKP"
  rect 0.8x3.5 smd paste-3.5 mask+0: 1(-1.27,1.35) 2(1.27,-1.35)
S2P_CN-5.08x2.54x9.65-PX2.54+18 [mm] "KC00080BKP"
  rect 0.8x3.5 smd paste-3.5 mask+0: 1(-1.27,1.35) 2(1.27,-1.35)
S2P_CN-5.08x2.54x9.65-PX2.54+19 [mm] "KC00080BKP"
  rect 0.8x3.5 smd paste-3.5 mask+0: 1(-1.27,1.35) 2(1.27,-1.35)
S2P_CN-5.08x2.54x9.65-PX2.54+20 [mm] "KC00080BKP"
  rect 0.8x3.5 smd paste-3.5 mask+0: 1(-1.27,1.35) 2(1.27,-1.35)
S2P_CN-5.08x2.54x9.65-PX2.54+21 [mm] "KC00080BKP"
  rect 0.8x3.5 smd paste-3.5 mask+0: 1(-1.27,1.35) 2(1.27,-1.35)
S2P_CN-5.08x2.54x9.65-PX2.54+22 [mm] "KC00080BKP"
  rect 0.8x3.5 smd paste-3.5 mask+0: 1(-1.27,1.35) 2(1.27,-1.35)
S2P_CN-5.08x2.54x9.65-PX2.54+23 [mm] "KC00080BKP"
  rect 0.8x3.5 smd paste-3.5 mask+0: 1(-1.27,1.35) 2(1.27,-1.35)
S2P_CN-5.08x2.54x9.65-PX2.54+24 [mm] "KC00080BKP"
  rect 0.8x3.5 smd paste-3.5 mask+0: 1(-1.27,1.35) 2(1.27,-1.35)
S2P_CN-5.08x2.54x9.65-PX2.54+25 [mm] "KC00080BKP"
  rect 0.8x3.5 smd paste-3.5 mask+0: 1(-1.27,1.35) 2(1.27,-1.35)
S2P_CN-5.08x2.54x9.65-PX2.54+26 [mm] "KC00080BKP"
  rect 0.8x3.5 smd paste-3.5 mask+0: 1(-1.27,1.35) 2(1.27,-1.35)
S2P_CN-5.08x2.54x9.65-PX2.54+27 [mm] "KC00080BKP"
  rect 0.8x3.5 smd paste-3.5 mask+0: 1(-1.27,1.35) 2(1.27,-1.35)
S2P_CN-5.08x2.54x9.65-PX2.54+28 [mm] "KC00080BKP"
  rect 0.8x3.5 smd paste-3.5 mask+0: 1(-1.27,1.35) 2(1.27,-1.35)
S2P_CN-5.08x2.54x9.65-PX2.54+29 [mm] "KC00080BKP"
  rect 0.8x3.5 smd paste-3.5 mask+0: 1(-1.27,1.35) 2(1.27,-1.35)
S2P_CN-5.08x2.54x9.65-PX2.54+30 [mm] "KC00080BKP"
  rect 0.8x3.5 smd paste-3.5 mask+0: 1(-1.27,1.35) 2(1.27,-1.35)
S2P_CN-5.08x2.54x9.65-PX2.54+31 [mm] "KC00080BKP"
  rect 0.8x3.5 smd paste-3.5 mask+0: 1(-1.27,1.35) 2(1.27,-1.35)
S2P_D-1.2x0.8x0.6-PX1.6 [mm] "KC00080BKP"
  rect 0.9x0.5 smd paste-0.9 mask+0: 1(0.85,0) 2(-0.85,0)
S2P_D-1.2x0.8x0.6-PX1.6+1 [mm] "KC00080BKP"
  rect 0.9x0.5 smd paste-0.9 mask+0: 1(0.85,0) 2(-0.85,0)
S2P_D-1.2x0.8x0.6-PX1.6+2 [mm] "KC00080BKP"
  rect 0.9x0.5 smd paste-0.9 mask+0: 1(0.85,0) 2(-0.85,0)
S2P_D-2.6x1.6x1-PX3.5 [mm] "KC00080BKP"
  rect 1.3x1.1 smd paste-1.3 mask+0: 1(-1.6,0) 2(1.6,0)
S2P_D-3.8x2.4x1-PX4.7 [mm] "KC00080BKP"
  rect 1.5x2.1 smd paste-2.1 mask+0: 1(2.15,0) 2(-2.15,0)
S2P_D-3.8x2.4x1-PX4.7+1 [mm] "KC00080BKP"
  rect 1.5x2.1 smd paste-2.1 mask+0: 1(-2.15,0) 2(2.15,0)
S2P_D-3.8x2.4x1-PX4.7+2 [mm] "KC00080BKP"
  rect 1.5x2.1 smd paste-2.1 mask+0: 1(-2.15,0) 2(2.15,0)
S2P_D-3.8x2.4x1-PX4.7+3 [mm] "KC00080BKP"
  rect 1.5x2.1 smd paste-2.1 mask+0: 1(2.15,0) 2(-2.15,0)
S2P_D-3.8x2.4x1-PX4.7+4 [mm] "KC00080BKP"
  rect 1.5x2.1 smd paste-2.1 mask+0: 1(-2.15,0) 2(2.15,0)
S2P_D-3.8x2.4x1-PX4.7+5 [mm] "KC00080BKP"
  rect 1.5x2.1 smd paste-2.1 mask+0: 1(2.15,0) 2(-2.15,0)
S2P_D-3.8x2.4x1-PX4.7+6 [mm] "KC00080BKP"
  rect 1.5x2.1 smd paste-2.1 mask+0: 1(2.15,0) 2(-2.15,0)
S2P_D-3.8x2.4x1-PX4.7+7 [mm] "KC00080BKP"
  rect 1.5x2.1 smd paste-2.1 mask+0: 1(2.15,0) 2(-2.15,0)
S2P_D-3.8x2.4x1-PX4.7+8 [mm] "KC00080BKP"
  rect 1.5x2.1 smd paste-2.1 mask+0: 1(-2.15,0) 2(2.15,0)
S2P_L-2x1.25x0.85-PX2 [mm] "KC00080BKP"
  rect 1x1.25 smd paste-1.25 mask+0: 1(1,0) 2(-1,0)
S2P_L-2x1.25x0.85-PX2+1 [mm] "KC00080BKP"
  rect 1x1.25 smd paste-1.25 mask+0: 1(1,0) 2(-1,0)
S2P_L-2x1.25x0.85-PX2+2 [mm] "KC00080BKP"
  rect 1x1.25 smd paste-1.25 mask+0: 1(1,0) 2(-1,0)
S2P_L-3.2x3.5x2-PX1.78 [mm] "KC00080BKP"
  rect 0.84x4.5 smd paste-4.5 mask+0: 1(-0.89,0) 2(0.89,0)
S2P_L-3x3x1.5-PX3 [mm] "KC00080BKP"
  rect 1.5x3.2 smd paste-3.2 mask+0: 1(1.25,0) 2(-1.25,0)
S2P_L-3x3x1.5-PX3+1 [mm] "KC00080BKP"
  rect 1.5x3.2 smd paste-3.2 mask+0: 1(1.25,0) 2(-1.25,0)
S2P_L-6.3x6x4.5-PX6.3 [mm] "KC00080BKP"
  rect 1.45x2.2 smd paste-2.2 mask+0: 1(-2.925,0) 2(2.925,0)
S2P_L-12.5x12.1x5.5-PX12.5 [mm] "KC00080BKP"
  rect 2.6x3.2 smd paste-3.2 mask+0: 1(-5.45,0) 2(5.45,0)
S2P_L-12.5x12.1x5.5-PX12.5+1 [mm] "KC00080BKP"
  rect 2.6x3.2 smd paste-3.2 mask+0: 1(-5.45,0) 2(5.45,0)
S2P_L-12.5x12.1x5.5-PX12.5+2 [mm] "KC00080BKP"
  rect 2.6x3.2 smd paste-3.2 mask+0: 1(-5.45,0) 2(5.45,0)
S2P_L-12.5x12.1x5.5-PX12.5+3 [mm] "KC00080BKP"
  rect 2.6x3.2 smd paste-3.2 mask+0: 1(-5.45,0) 2(5.45,0)
S2P_L-12.5x12.1x5.5-PX12.5+4 [mm] "KC00080BKP"
  rect 2.6x3.2 smd paste-3.2 mask+0: 1(-5.45,0) 2(5.45,0)
S2P_L-12.5x12.1x5.5-PX12.5+5 [mm] "KC00080BKP"
  rect 2.6x3.2 smd paste-3.2 mask+0: 1(-5.45,0) 2(5.45,0)
S2P_L-12.5x12.1x5.5-PX12.5+6 [mm] "KC00080BKP"
  rect 2.6x3.2 smd paste-3.2 mask+0: 1(-5.45,0) 2(5.45,0)
S2P_L-12.5x12.1x5.5-PX12.5+7 [mm] "KC00080BKP"
  rect 2.6x3.2 smd paste-3.2 mask+0: 1(-5.45,0) 2(5.45,0)
S2P_L-12.5x12.1x5.5-PX12.5+8 [mm] "KC00080BKP"
  rect 2.6x3.2 smd paste-3.2 mask+0: 1(-5.45,0) 2(5.45,0)
S2P_L-12.5x12.1x5.5-PX12.5+9 [mm] "KC00080BKP"
  rect 2.6x3.2 smd paste-3.2 mask+0: 1(-5.45,0) 2(5.45,0)
S2P_L-12.5x12.1x5.5-PX12.5+10 [mm] "KC00080BKP"
  rect 2.6x3.2 smd paste-3.2 mask+0: 1(-5.45,0) 2(5.45,0)
S2P_L-12.5x12.1x5.5-PX12.5+11 [mm] "KC00080BKP"
  rect 2.6x3.2 smd paste-3.2 mask+0: 1(-5.45,0) 2(5.45,0)
S2P_L-12.5x12.1x5.5-PX12.5+12 [mm] "KC00080BKP"
  rect 2.6x3.2 smd paste-3.2 mask+0: 1(-5.45,0) 2(5.45,0)
S2P_L-12.5x12.1x5.5-PX12.5+13 [mm] "KC00080BKP"
  rect 2.6x3.2 smd paste-3.2 mask+0: 1(-5.45,0) 2(5.45,0)
S2P_L-12.5x12.1x5.5-PX12.5+14 [mm] "KC00080BKP"
  rect 2.6x3.2 smd paste-3.2 mask+0: 1(-5.45,0) 2(5.45,0)
S2P_L-12.5x12.1x5.5-PX12.5+15 [mm] "KC00080BKP"
  rect 2.6x3.2 smd paste-3.2 mask+0: 1(-5.45,0) 2(5.45,0)
S2P_L-12.5x12.1x5.5-PX12.5+16 [mm] "KC00080BKP"
  rect 2.6x3.2 smd paste-3.2 mask+0: 1(-5.45,0) 2(5.45,0)
S2P_L-12.5x12.1x5.5-PX12.5+17 [mm] "KC00080BKP"
  rect 2.6x3.2 smd paste-3.2 mask+0: 1(-5.45,0) 2(5.45,0)
S2P_L-12.5x12.1x5.5-PX12.5+18 [mm] "KC00080BKP"
  rect 2.6x3.2 smd paste-3.2 mask+0: 1(-5.45,0) 2(5.45,0)
S2P_L-12.5x12.1x5.5-PX12.5+19 [mm] "KC00080BKP"
  rect 2.6x3.2 smd paste-3.2 mask+0: 1(-5.45,0) 2(5.45,0)
S2P_L-12x12x7.8-PY12 [mm] "KC00080BKP"
  rect 5.2x3 smd paste-5.2 mask+0: 1(0,-5) 2(0,5)
S2P_ZD-2x1.4x0.6-PX2.5 [mm] "KC00080BKP"
  rect 1x1.2 smd paste-1.2 mask+0: 1(1.25,0)
  rect 2.1x1.2 smd paste-2.1 mask+0: 2(-0.7,0)
S3P_Q-2.0x1.25x0.9-PX0.65-PY2.1 [mm] "KC00080BKP"
  rect 0.5x0.9 smd paste-0.9 mask+0: 1(-0.65,-1.1) 2(0.65,-1.1) 3(0,1.1)
S3P_Q-2.0x1.25x0.9-PX0.65-PY2.1+1 [mm] "KC00080BKP"
  rect 0.5x0.9 smd paste-0.9 mask+0: 1(-0.65,-1.1) 2(0.65,-1.1) 3(0,1.1)
S3P_Q-2.0x1.25x0.9-PX0.65-PY2.1+2 [mm] "KC00080BKP"
  rect 0.5x0.9 smd paste-0.9 mask+0: 1(-0.65,-1.1) 2(0.65,-1.1) 3(0,1.1)
S3P_Q-2.0x1.25x0.9-PX0.65-PY2.1+3 [mm] "KC00080BKP"
  rect 0.5x0.9 smd paste-0.9 mask+0: 1(-0.65,-1.1) 2(0.65,-1.1) 3(0,1.1)
S3P_Q-2.0x1.25x0.9-PX0.65-PY2.1+4 [mm] "KC00080BKP"
  rect 0.5x0.9 smd paste-0.9 mask+0: 1(-0.65,-1.1) 2(0.65,-1.1) 3(0,1.1)
S3P_Q-2.0x1.25x0.9-PX0.65-PY2.1+5 [mm] "KC00080BKP"
  rect 0.5x0.9 smd paste-0.9 mask+0: 1(-0.65,-1.1) 2(0.65,-1.1) 3(0,1.1)
S3P_Q-2.0x1.25x0.9-PX0.65-PY2.1+6 [mm] "KC00080BKP"
  rect 0.5x0.9 smd paste-0.9 mask+0: 1(-0.65,-1.1) 2(0.65,-1.1) 3(0,1.1)
S3P_Q-2.0x1.25x0.9-PX0.65-PY2.1+7 [mm] "KC00080BKP"
  rect 0.5x0.9 smd paste-0.9 mask+0: 1(-0.65,-1.1) 2(0.65,-1.1) 3(0,1.1)
S3P_Q-2.0x1.25x0.9-PX0.65-PY2.1+8 [mm] "KC00080BKP"
  rect 0.5x0.9 smd paste-0.9 mask+0: 1(-0.65,-1.1) 2(0.65,-1.1) 3(0,1.1)
S3P_Q-2.0x1.25x0.9-PX0.65-PY2.1+9 [mm] "KC00080BKP"
  rect 0.5x0.9 smd paste-0.9 mask+0: 1(-0.65,-1.1) 2(0.65,-1.1) 3(0,1.1)
S3P_Q-2.0x1.25x0.9-PX0.65-PY2.1+10 [mm] "KC00080BKP"
  rect 0.5x0.9 smd paste-0.9 mask+0: 1(-0.65,-1.1) 2(0.65,-1.1) 3(0,1.1)
S3P_Q-2.0x1.25x0.9-PX0.65-PY2.1+11 [mm] "KC00080BKP"
  rect 0.5x0.9 smd paste-0.9 mask+0: 1(-0.65,-1.1) 2(0.65,-1.1) 3(0,1.1)
S3P_Q-2.0x1.25x0.9-PX0.65-PY2.1+12 [mm] "KC00080BKP"
  rect 0.5x0.9 smd paste-0.9 mask+0: 1(-0.65,-1.1) 2(0.65,-1.1) 3(0,1.1)
S3P_Q-2.0x1.25x0.9-PX0.65-PY2.1+13 [mm] "KC00080BKP"
  rect 0.5x0.9 smd paste-0.9 mask+0: 1(-0.65,-1.1) 2(0.65,-1.1) 3(0,1.1)
S3P_Q-2.0x1.25x0.9-PX0.65-PY2.1+14 [mm] "KC00080BKP"
  rect 0.5x0.9 smd paste-0.9 mask+0: 1(-0.65,-1.1) 2(0.65,-1.1) 3(0,1.1)
S3P_Q-2.0x1.25x0.9-PX0.65-PY2.1+15 [mm] "KC00080BKP"
  rect 0.5x0.9 smd paste-0.9 mask+0: 1(-0.65,-1.1) 2(0.65,-1.1) 3(0,1.1)
S3P_Q-2.0x1.25x0.9-PX0.65-PY2.1+16 [mm] "KC00080BKP"
  rect 0.5x0.9 smd paste-0.9 mask+0: 1(-0.65,-1.1) 2(0.65,-1.1) 3(0,1.1)
S3P_Q-2.0x1.25x0.9-PX0.65-PY2.1+17 [mm] "KC00080BKP"
  rect 0.5x0.9 smd paste-0.9 mask+0: 1(-0.65,-1.1) 2(0.65,-1.1) 3(0,1.1)
S3P_Q-2.0x1.25x0.9-PX0.65-PY2.1+18 [mm] "KC00080BKP"
  rect 0.5x0.9 smd paste-0.9 mask+0: 1(-0.65,-1.1) 2(0.65,-1.1) 3(0,1.1)
S3P_Q-2.0x1.25x0.9-PX0.65-PY2.1+19 [mm] "KC00080BKP"
  rect 0.5x0.9 smd paste-0.9 mask+0: 1(-0.65,-1.1) 2(0.65,-1.1) 3(0,1.1)
S3P_Q-2.0x1.25x0.9-PX0.65-PY2.1+20 [mm] "KC00080BKP"
  rect 0.5x0.9 smd paste-0.9 mask+0: 1(-0.65,-1.1) 2(0.65,-1.1) 3(0,1.1)
S3P_Q-2.0x1.25x0.9-PX0.65-PY2.1+21 [mm] "KC00080BKP"
  rect 0.5x0.9 smd paste-0.9 mask+0: 1(-0.65,-1.1) 2(0.65,-1.1) 3(0,1.1)
S3P_Q-2.0x1.25x0.9-PX0.65-PY2.1+22 [mm] "KC00080BKP"
  rect 0.5x0.9 smd paste-0.9 mask+0: 1(-0.65,-1.1) 2(0.65,-1.1) 3(0,1.1)
S3P_Q-2.0x1.25x0.9-PX0.65-PY2.1+23 [mm] "KC00080BKP"
  rect 0.5x0.9 smd paste-0.9 mask+0: 1(-0.65,-1.1) 2(0.65,-1.1) 3(0,1.1)
S3P_Q-2.0x1.25x0.9-PX0.65-PY2.1+24 [mm] "KC00080BKP"
  rect 0.5x0.9 smd paste-0.9 mask+0: 1(-0.65,-1.1) 2(0.65,-1.1) 3(0,1.1)
S3P_Q-2.0x1.25x0.9-PX0.65-PY2.1+25 [mm] "KC00080BKP"
  rect 0.5x0.9 smd paste-0.9 mask+0: 1(-0.65,-1.1) 2(0.65,-1.1) 3(0,1.1)
S3P_Q-2.0x1.25x0.9-PX0.65-PY2.1+26 [mm] "KC00080BKP"
  rect 0.5x0.9 smd paste-0.9 mask+0: 1(-0.65,-1.1) 2(0.65,-1.1) 3(0,1.1)
S3P_Q-2.0x1.25x0.9-PX0.65-PY2.1+27 [mm] "KC00080BKP"
  rect 0.5x0.9 smd paste-0.9 mask+0: 1(-0.65,-1.1) 2(0.65,-1.1) 3(0,1.1)
S3P_Q-2.0x1.25x0.9-PX0.65-PY2.1+28 [mm] "KC00080BKP"
  rect 0.5x0.9 smd paste-0.9 mask+0: 1(-0.65,-1.1) 2(0.65,-1.1) 3(0,1.1)
S3P_Q-2.0x1.25x0.9-PX0.65-PY2.1+29 [mm] "KC00080BKP"
  rect 0.5x0.9 smd paste-0.9 mask+0: 1(-0.65,-1.1) 2(0.65,-1.1) 3(0,1.1)
S3P_Q-2.0x1.25x0.9-PX0.65-PY2.1+30 [mm] "KC00080BKP"
  rect 0.5x0.9 smd paste-0.9 mask+0: 1(-0.65,-1.1) 2(0.65,-1.1) 3(0,1.1)
S3P_U-6.53x3.43x1.8-PX2.3-PY7 [mm] "KC00080BKP"
  rect 0.9x1.5 smd paste-1.5 mask+0: 1(-2.3,-3.25) 3(2.3,-3.25)
  round 0.178 smd paste-0.178 mask+0: 2(0,-3.25)
S3P_U-6.53x3.43x1.8-PX2.3-PY7+1 [mm] "KC00080BKP"
  rect 0.9x1.5 smd paste-1.5 mask+0: 1(-2.3,-3.25) 3(2.3,-3.25)
  round 0.178 smd paste-0.178 mask+0: 2(0,-3.25)
S3P_U-6.53x3.43x1.8-PX2.3-PY7+2 [mm] "KC00080BKP"
  rect 0.9x1.5 smd paste-1.5 mask+0: 1(-2.3,-3.25) 3(2.3,-3.25)
  round 0.178 smd paste-0.178 mask+0: 2(0,-3.25)
S3P_U-6.53x3.43x1.8-PX2.3-PY7+3 [mm] "KC00080BKP"
  rect 0.9x1.5 smd paste-1.5 mask+0: 1(-2.3,-3.25) 3(2.3,-3.25)
  round 0.178 smd paste-0.178 mask+0: 2(0,-3.25)
S5P_U-2x1.25x1-PX0.65-PY2.1 [mm] "KC00080BKP"
  rect 0.3x0.9 smd paste-0.9 mask+0: 1(-0.65,-1.1) 2(0,-1.1) 3(0.65,-1.1) 4(0.65,1.1) 5(-0.65,1.1)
